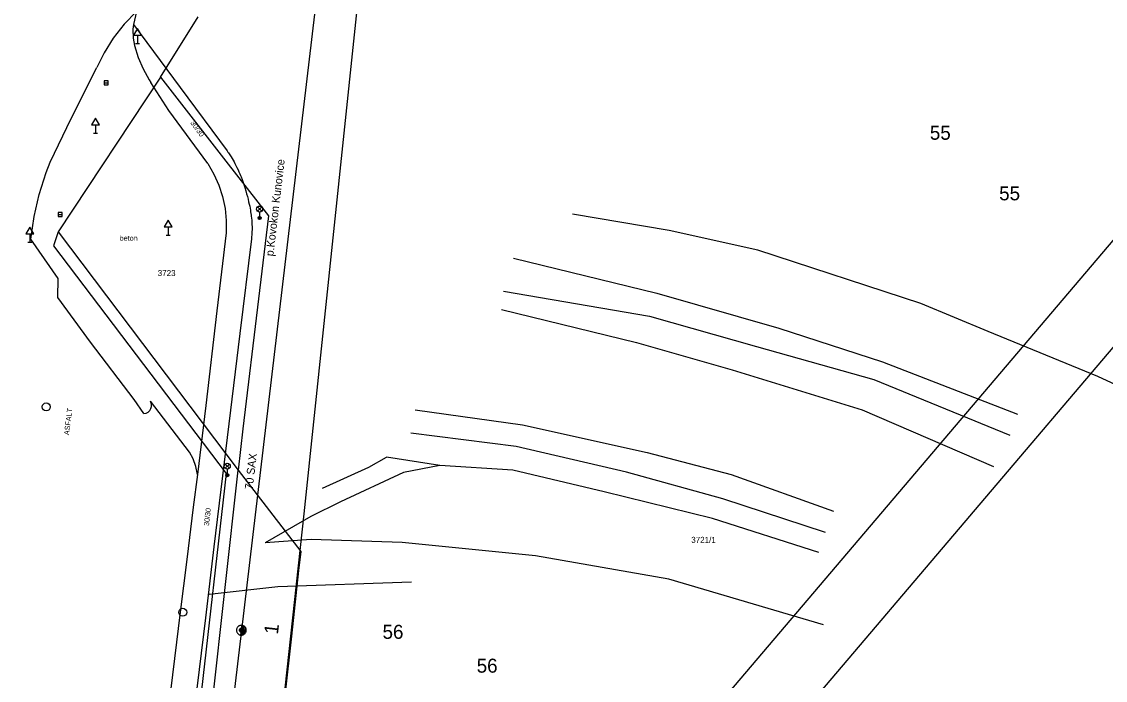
# Model space of a CAD drawing. Extents: x -540150 to -533593, y -1185082 to -1180066.
# Drawn here: x -536575.8 to -536440.4, y -1182958.7 to -1182876.4 of the extents above; entities that cross this region are included whole.
import ezdxf

# ---------------------------------------------------------------- set-up
doc = ezdxf.new("R2010")
doc.units = 0
for name, color, linetype in [('KN_HRAN_PARCEL', 7, 'Continuous'), ('KN_PARC_Č', 7, 'Continuous'), ('KN_VKP_HRAN_', 7, 'Continuous'), ('rámeček', 7, 'Continuous'), ('Vrstva 10', 7, 'Continuous'), ('Vrstva 11', 7, 'Continuous'), ('Vrstva 13', 7, 'Continuous'), ('Vrstva 14', 7, 'Continuous'), ('Vrstva 2', 7, 'Continuous'), ('Vrstva 25', 7, 'Continuous'), ('Vrstva 27', 7, 'Continuous'), ('Vrstva 33', 7, 'Continuous'), ('Vrstva 34', 7, 'Continuous'), ('Vrstva 4', 7, 'Continuous'), ('Vrstva 40', 7, 'Continuous'), ('Vrstva 57', 7, 'Continuous'), ('Vrstva 59', 7, 'Continuous'), ('Vrstva 7', 7, 'Continuous')]:
    doc.layers.add(name, color=color, linetype=linetype)

# ---------------------------------------------------------------- blocks, each defined once
blk = doc.blocks.new('VN440')
at = {"layer": 'Vrstva 2'}
for points in [[(1.22, 0), (1.21, 0.13), (1.19, 0.25), (1.16, 0.38), (1.11, 0.5), (1.05, 0.61), (0.98, 0.72), (0.9, 0.82), (0.81, 0.91), (0.71, 0.99), (0.6, 1.06), (0.49, 1.12), (0.37, 1.16), (0.25, 1.2), (0.12, 1.22), (-0.01, 1.22), (-0.14, 1.22), (-0.26, 1.2), (-0.39, 1.16), (-0.51, 1.12), (-0.62, 1.06), (-0.73, 0.99), (-0.83, 0.91), (-0.92, 0.82), (-1, 0.72), (-1.07, 0.61), (-1.13, 0.5), (-1.18, 0.38), (-1.21, 0.25), (-1.23, 0.13), (-1.24, 0), (-1.23, -0.13), (-1.21, -0.26), (-1.18, -0.38), (-1.13, -0.5), (-1.07, -0.62), (-1, -0.73), (-0.92, -0.83), (-0.83, -0.92), (-0.73, -1), (-0.62, -1.07), (-0.51, -1.13), (-0.39, -1.17), (-0.26, -1.2), (-0.14, -1.23), (-0.01, -1.23), (0.12, -1.23), (0.25, -1.2), (0.37, -1.17), (0.49, -1.13), (0.6, -1.07), (0.71, -1), (0.81, -0.92), (0.9, -0.83), (0.98, -0.73), (1.05, -0.62), (1.11, -0.5), (1.16, -0.38), (1.19, -0.26), (1.21, -0.13), (1.22, 0)], [(-1.24, 0), (1.22, 0)], [(-1.18, -0.34), (1.1, -0.34)], [(-1.01, -0.63), (0.97, -0.63)], [(-0.74, -0.92), (0.68, -0.92)]]:
    blk.add_lwpolyline(points, dxfattribs=at)

msp = doc.modelspace()

# ---------------------------------------------------------------- linework, layer by layer
at = {"layer": 'KN_HRAN_PARCEL'}
for p, q in [((-536558.46, -1182883.28), (-536553.77, -1182875.77)), ((-536558.46, -1182883.28), (-536571.26, -1182902.62)), ((-536558.46, -1182883.28), (-536550.32, -1182893.79)), ((-536550.32, -1182893.79), (-536545, -1182900.65)), ((-536545, -1182900.65), (-536546.23, -1182911)), ((-536571.26, -1182902.62), (-536571.84, -1182904.39)), ((-536571.26, -1182902.62), (-536548.79, -1182932.43)), ((-536571.84, -1182904.39), (-536550.27, -1182932.85)), ((-536546.23, -1182911), (-536548.17, -1182927.25)), ((-536548.17, -1182927.25), (-536548.79, -1182932.43)), ((-536550.27, -1182932.85), (-536559.91, -1183017.15)), ((-536548.79, -1182932.43), (-536540.96, -1182942.59)), ((-536540.96, -1182942.59), (-536541.22, -1182944.95)), ((-536541.22, -1182944.95), (-536542.12, -1182953.17)), ((-536542.12, -1182953.17), (-536542.99, -1182961.02))]:
    msp.add_line(p, q, dxfattribs=at)
at = {"layer": 'KN_VKP_HRAN_'}
msp.add_line((-536558.2, -1183017.36), (-536548.79, -1182932.43), dxfattribs=at)
at = {"layer": 'rámeček'}
msp.add_lwpolyline([(-536738.71, -1183256.04), (-536957.47, -1183070.27), (-535604.64, -1181477.18), (-535385.87, -1181662.95)], close=True, dxfattribs=at)
msp.add_lwpolyline([(-535379.29, -1181668.54), (-536732.12, -1183261.63), (-536513.36, -1183447.4), (-535160.52, -1181854.31)], dxfattribs=at)
at = {"layer": 'Vrstva 10'}
for p, q in [((-536569.62, -1182888.45), (-536566.42, -1182882.1)), ((-536557.45, -1182887.48), (-536559.66, -1182883.98)), ((-536572.26, -1182893.94), (-536569.62, -1182888.45)), ((-536552.58, -1182894.09), (-536557.45, -1182887.48)), ((-536550.25, -1182902.77), (-536551.42, -1182912.52)), ((-536571.27, -1182908.47), (-536574.68, -1182903.56)), ((-536571.29, -1182910.82), (-536571.27, -1182908.47)), ((-536567.2, -1182916.41), (-536571.29, -1182910.82)), ((-536551.42, -1182912.52), (-536552.83, -1182924.35)), ((-536561.78, -1182923.6), (-536567.2, -1182916.41)), ((-536560.56, -1182925.32), (-536561.78, -1182923.6)), ((-536554.86, -1182930.16), (-536559.72, -1182923.8)), ((-536552.83, -1182924.35), (-536553.87, -1182932.95)), ((-536553.87, -1182932.95), (-536554.38, -1182937.03)), ((-536554.38, -1182937.03), (-536555.19, -1182943.6)), ((-536555.19, -1182943.6), (-536556, -1182950.17)), ((-536556, -1182950.17), (-536557.66, -1182963.58))]:
    msp.add_line(p, q, dxfattribs=at)
for points in [[(-536561.48, -1182875.1), (-536563.02, -1182876.67), (-536564.37, -1182878.4), (-536565.53, -1182880.26), (-536566.42, -1182882.1)], [(-536561.48, -1182875.1), (-536561.86, -1182876.71), (-536561.91, -1182877.29), (-536561.88, -1182878.4), (-536561.74, -1182879.32)], [(-536561.74, -1182879.32), (-536561.27, -1182880.82), (-536560.65, -1182882.26), (-536559.89, -1182883.62), (-536559.66, -1182883.98)], [(-536574.68, -1182903.56), (-536574.27, -1182900.73), (-536573.63, -1182897.95), (-536572.76, -1182895.23), (-536572.26, -1182893.94)], [(-536552.58, -1182894.09), (-536551.82, -1182895.4), (-536551.2, -1182896.79), (-536550.72, -1182898.23), (-536550.41, -1182899.72), (-536550.25, -1182901.23), (-536550.25, -1182902.74), (-536550.25, -1182902.77)], [(-536560.56, -1182925.32), (-536560.28, -1182925.28), (-536560.03, -1182925.16), (-536559.81, -1182924.97), (-536559.66, -1182924.73), (-536559.58, -1182924.46), (-536559.59, -1182924.18), (-536559.66, -1182923.91), (-536559.72, -1182923.8)], [(-536553.87, -1182932.95), (-536554.05, -1182931.97), (-536554.39, -1182931.02), (-536554.86, -1182930.16)]]:
    msp.add_lwpolyline(points, dxfattribs=at)
at = {"layer": 'Vrstva 11'}
for p, q in [((-536561.86, -1182876.71), (-536556.02, -1182884.6)), ((-536556.02, -1182884.6), (-536550.16, -1182892.52)), ((-536547.12, -1182903.5), (-536548.55, -1182915.35)), ((-536548.55, -1182915.35), (-536550.72, -1182933.13)), ((-536550.72, -1182933.13), (-536551.79, -1182942.01)), ((-536551.79, -1182942.01), (-536552.87, -1182950.9)), ((-536552.87, -1182950.9), (-536554.49, -1182964.33))]:
    msp.add_line(p, q, dxfattribs=at)
for points in [[(-536550.16, -1182892.52), (-536550.07, -1182892.65), (-536549.98, -1182892.77), (-536549.81, -1182893.02), (-536549.66, -1182893.25), (-536549.52, -1182893.47), (-536549.4, -1182893.68), (-536549.29, -1182893.88), (-536549.19, -1182894.07), (-536549.09, -1182894.25), (-536549.01, -1182894.41), (-536548.93, -1182894.57), (-536548.79, -1182894.87), (-536548.67, -1182895.14), (-536548.57, -1182895.38), (-536548.49, -1182895.59), (-536548.41, -1182895.77), (-536548.29, -1182896.09), (-536548.2, -1182896.34), (-536548.07, -1182896.71), (-536547.95, -1182897.09), (-536547.83, -1182897.49), (-536547.72, -1182897.87), (-536547.62, -1182898.22), (-536547.53, -1182898.55), (-536547.46, -1182898.86), (-536547.39, -1182899.15), (-536547.33, -1182899.42), (-536547.29, -1182899.68), (-536547.24, -1182899.91), (-536547.21, -1182900.14), (-536547.18, -1182900.35), (-536547.15, -1182900.55), (-536547.13, -1182900.73), (-536547.11, -1182900.9), (-536547.08, -1182901.23), (-536547.06, -1182901.51), (-536547.05, -1182901.76)], [(-536547.05, -1182901.76), (-536547.04, -1182901.98), (-536547.04, -1182902.17), (-536547.04, -1182902.34), (-536547.05, -1182902.63), (-536547.06, -1182902.85), (-536547.07, -1182903.01), (-536547.09, -1182903.26), (-536547.12, -1182903.5)]]:
    msp.add_lwpolyline(points, dxfattribs=at)
at = {"layer": 'Vrstva 14'}
for points in [[(-536402.53, -1182937.46), (-536428.44, -1182926.71), (-536441.38, -1182920.72), (-536455.07, -1182915.07), (-536463.51, -1182911.6), (-536483.86, -1182904.94), (-536494.91, -1182902.45), (-536507, -1182900.44)], [(-536514.37, -1182905.92), (-536496.45, -1182910.28), (-536481.24, -1182914.68), (-536468.29, -1182918.9), (-536451.43, -1182925.44)], [(-536515.62, -1182910.06), (-536497.38, -1182913.17), (-536484.02, -1182916.97), (-536469.38, -1182921.08), (-536452.39, -1182928.04)], [(-536515.87, -1182912.35), (-536498.99, -1182916.46), (-536487.08, -1182919.87), (-536470.81, -1182924.87), (-536454.41, -1182931.95)], [(-536526.68, -1182924.9), (-536513.25, -1182926.77), (-536497.68, -1182930.2), (-536487.17, -1182932.96), (-536474.41, -1182937.54)], [(-536475.41, -1182940.21), (-536488.24, -1182935.99), (-536500.25, -1182932.66), (-536514.05, -1182929.47), (-536527.21, -1182927.81)], [(-536523.57, -1182931.83), (-536528.12, -1182932.73), (-536535.99, -1182936.4), (-536539.68, -1182938.23), (-536545.38, -1182941.52)], [(-536538.23, -1182934.68), (-536532.44, -1182932.04), (-536530.23, -1182930.8)], [(-536523.57, -1182931.83), (-536530.23, -1182930.8)], [(-536476.24, -1182942.71), (-536489.5, -1182938.46), (-536503.03, -1182935.13), (-536514.44, -1182932.44), (-536523.57, -1182931.83)], [(-536475.67, -1182951.78), (-536494.99, -1182946.05), (-536511.64, -1182943.15), (-536528.27, -1182941.47), (-536539.66, -1182941.09), (-536545.38, -1182941.52)], [(-536552.41, -1182947.92), (-536543.8, -1182946.95), (-536527.12, -1182946.38)]]:
    msp.add_lwpolyline(points, dxfattribs=at)
at = {"layer": 'Vrstva 25'}
for radius in [0.25, 0.2, 0.15, 0.1, 0.05]:
    msp.add_circle((-536548.37, -1182952.43), radius, dxfattribs=at)
at = {"layer": 'Vrstva 27'}
for p, q in [((-536565.51, -1182884), (-536565.01, -1182884)), ((-536571.24, -1182900.48), (-536570.74, -1182900.48))]:
    msp.add_line(p, q, dxfattribs=at)
for points in [[(-536565.51, -1182884.25), (-536565.01, -1182884.25), (-536565.01, -1182883.75), (-536565.51, -1182883.75)], [(-536571.24, -1182900.73), (-536570.74, -1182900.73), (-536570.74, -1182900.23), (-536571.24, -1182900.23)]]:
    msp.add_lwpolyline(points, close=True, dxfattribs=at)
for centre in [(-536572.75, -1182924.51), (-536555.69, -1182950.19)]:
    msp.add_circle(centre, 0.5, dxfattribs=at)
at = {"layer": 'Vrstva 33'}
for p, q in [((-536546.35, -1182900.04), (-536545.82, -1182899.51)), ((-536546.35, -1182899.51), (-536545.82, -1182900.04)), ((-536546.09, -1182900.15), (-536546.09, -1182900.9)), ((-536550.39, -1182932.19), (-536549.86, -1182931.66)), ((-536550.39, -1182931.66), (-536549.86, -1182932.19)), ((-536550.13, -1182932.3), (-536550.13, -1182933.05))]:
    msp.add_line(p, q, dxfattribs=at)
for centre, radius in [((-536546.09, -1182899.78), 0.375), ((-536546.09, -1182900.9), 0.2), ((-536546.09, -1182900.9), 0.145), ((-536546.09, -1182900.9), 0.0876), ((-536550.13, -1182931.93), 0.375), ((-536550.13, -1182933.05), 0.2), ((-536550.13, -1182933.05), 0.145), ((-536550.13, -1182933.05), 0.0876)]:
    msp.add_circle(centre, radius, dxfattribs=at)
at = {"layer": 'Vrstva 34'}
for p, q in [((-536561.6, -1182879.08), (-536561.1, -1182879.08)), ((-536561.35, -1182878.06), (-536561.35, -1182879.08)), ((-536566.61, -1182889.27), (-536566.61, -1182890.29)), ((-536566.86, -1182890.29), (-536566.36, -1182890.29)), ((-536557.5, -1182902.02), (-536557.5, -1182903.04)), ((-536574.81, -1182902.89), (-536574.81, -1182903.91)), ((-536557.75, -1182903.04), (-536557.25, -1182903.04)), ((-536575.06, -1182903.91), (-536574.56, -1182903.91))]:
    msp.add_line(p, q, dxfattribs=at)
for points in [[(-536561.85, -1182878.06), (-536560.85, -1182878.06), (-536561.35, -1182877.2)], [(-536567.11, -1182889.27), (-536566.11, -1182889.27), (-536566.61, -1182888.41)], [(-536575.31, -1182902.89), (-536574.31, -1182902.89), (-536574.81, -1182902.03)], [(-536558, -1182902.02), (-536557, -1182902.02), (-536557.5, -1182901.16)]]:
    msp.add_lwpolyline(points, close=True, dxfattribs=at)
at = {"layer": 'Vrstva 4'}
msp.add_lwpolyline([(-536659.85, -1182853.42), (-536606.93, -1182849.26), (-536538.21, -1182866.58), (-536548.37, -1182952.43), (-536556.14, -1183018), (-536538.4, -1183020.16)], dxfattribs=at)
at = {"layer": 'Vrstva 7'}
msp.add_lwpolyline([(-536549.94, -1183024.44), (-536549.3, -1183018.54), (-536540.54, -1182937.9), (-536533.01, -1182866.45), (-536531.45, -1182851.44)], dxfattribs=at)

# ---------------------------------------------------------------- block references
at = {"layer": 'Vrstva 13', "xscale": 0.5, "yscale": 0.5, "rotation": 83.24200278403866}
msp.add_blockref('VN440', (-536548.37, -1182952.43), dxfattribs=at)

# ---------------------------------------------------------------- texts
at = {"layer": 'KN_PARC_Č'}
for s, p in [('3723', (-536558.82, -1182908.16)), ('3721/1', (-536492.17, -1182941.51))]:
    msp.add_text(s, height=0.75, dxfattribs=at).set_placement(p)
at = {"layer": 'Vrstva 14'}
for s, p in [('55', (-536462.36, -1182891.12)), ('55', (-536453.7, -1182898.69)), ('56', (-536530.73, -1182953.51)), ('56', (-536518.97, -1182957.74))]:
    msp.add_text(s, height=1.75, dxfattribs=at).set_placement(p)
msp.add_text('1', height=1.75, rotation=83.242, dxfattribs=at).set_placement((-536543.81, -1182953.02))
at = {"layer": 'Vrstva 40'}
for s, rotation, p in [('30/30', 306.4977, (-536554.79, -1182889.02)), ('ASFALT', 83.0752, (-536569.89, -1182928.07)), ('30/30', 83.0356, (-536552.43, -1182939.43))]:
    msp.add_text(s, height=0.65, rotation=rotation, dxfattribs=at).set_placement(p)
msp.add_text('beton', height=0.65, dxfattribs=at).set_placement((-536563.57, -1182903.75))
at = {"layer": 'Vrstva 57'}
msp.add_text('70 SAX', height=1, rotation=83.251, dxfattribs=at).set_placement((-536546.96, -1182934.89))
at = {"layer": 'Vrstva 59'}
msp.add_text('p.Kovokon Kunovice', height=1, rotation=83.251, dxfattribs=at).set_placement((-536544.38, -1182905.72))

doc.saveas('drawing.dxf')
